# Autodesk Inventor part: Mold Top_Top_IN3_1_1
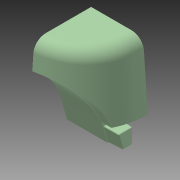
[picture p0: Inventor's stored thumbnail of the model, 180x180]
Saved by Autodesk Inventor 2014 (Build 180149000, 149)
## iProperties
Created: 2009-12
Part Number: Mold Top_Top_IN3_1_1
Document SubType Name: Modeling
Designer: gaom
Density: 1 g/cm^3
Material: Generic
Appearance: Green Pastel
Author: gaom
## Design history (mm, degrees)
node "Mold Top_Top_IN3_Base"
feature "Solid6::Mold Top_Top_IN3_Base"
tag "TaggingFeature1"
body "Solid1"
